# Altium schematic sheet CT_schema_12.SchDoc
size 145 x 119 mm
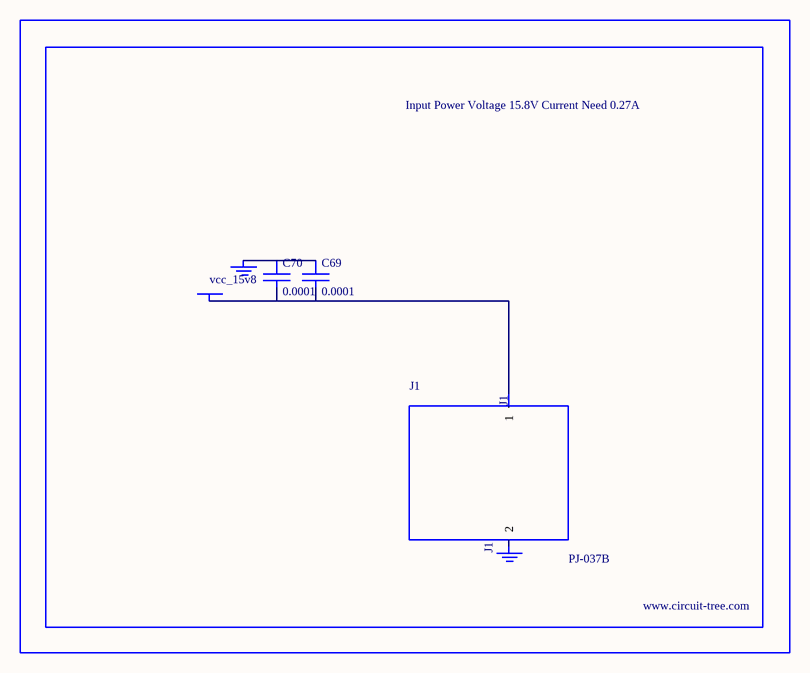
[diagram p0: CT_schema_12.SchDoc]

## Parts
BORDER11  (no value)
C69  0.0001  [EXV-9H]
C70  0.0001  [EXV-9H]
GND_INSTANCE_11_0  (no value)
GND_INSTANCE_11_1  (no value)
J1  PJ-037B  [PJ-037B_PACKAGE]
POWER_INSTANCE_11_0  vcc_15v8

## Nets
NetC69_1: C69.1 C70.1 GND_INSTANCE_11_0.0(GND)
NetC69_2: C69.2 C70.2 J1.1 POWER_INSTANCE_11_0.0(PWR)

Not connected (* = marked no-connect by the designer): GND_INSTANCE_11_1 0(GND); J1 2

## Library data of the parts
BORDER11 = BORDER_PAGE11
C69 C70 = EDK107M035A9HAA
GND_INSTANCE_11_0 GND_INSTANCE_11_1 = GND
POWER_INSTANCE_11_0 = PWR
